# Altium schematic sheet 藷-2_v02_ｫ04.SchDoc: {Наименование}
size 420 x 297 mm; DrawnBy: Булычев; Engineer: {Инженер}; DocumentNumber: СИЭТ 21.02.110.000 Э3; SheetNumber: 4; SheetTotal: 6; Title1str: Плата управления; PageSetup: Record=PageOptions|CenterHorizontal=False|CenterVertical=False|PrintScale=0.95|XCorrection=1.00|YCorrection=1.00|PrintKind=2|BorderSize=5000000|LeftOffset=300|BottomOffset=0|Orientation=2|PaperLength=4200|PaperWidth=2970|Scale=100|PaperSource=15|PrintQuality=-1|MediaType=1|DitherType=10|PaperKind=ISO A3|PrintScaleMode=1; Title2str: (ПУ-2); EngineerName: {Инженер}; DocumentType: Схема электрическая принципиальная; DocumentType1str: {Документ}; DocumentType2str: {Документ}
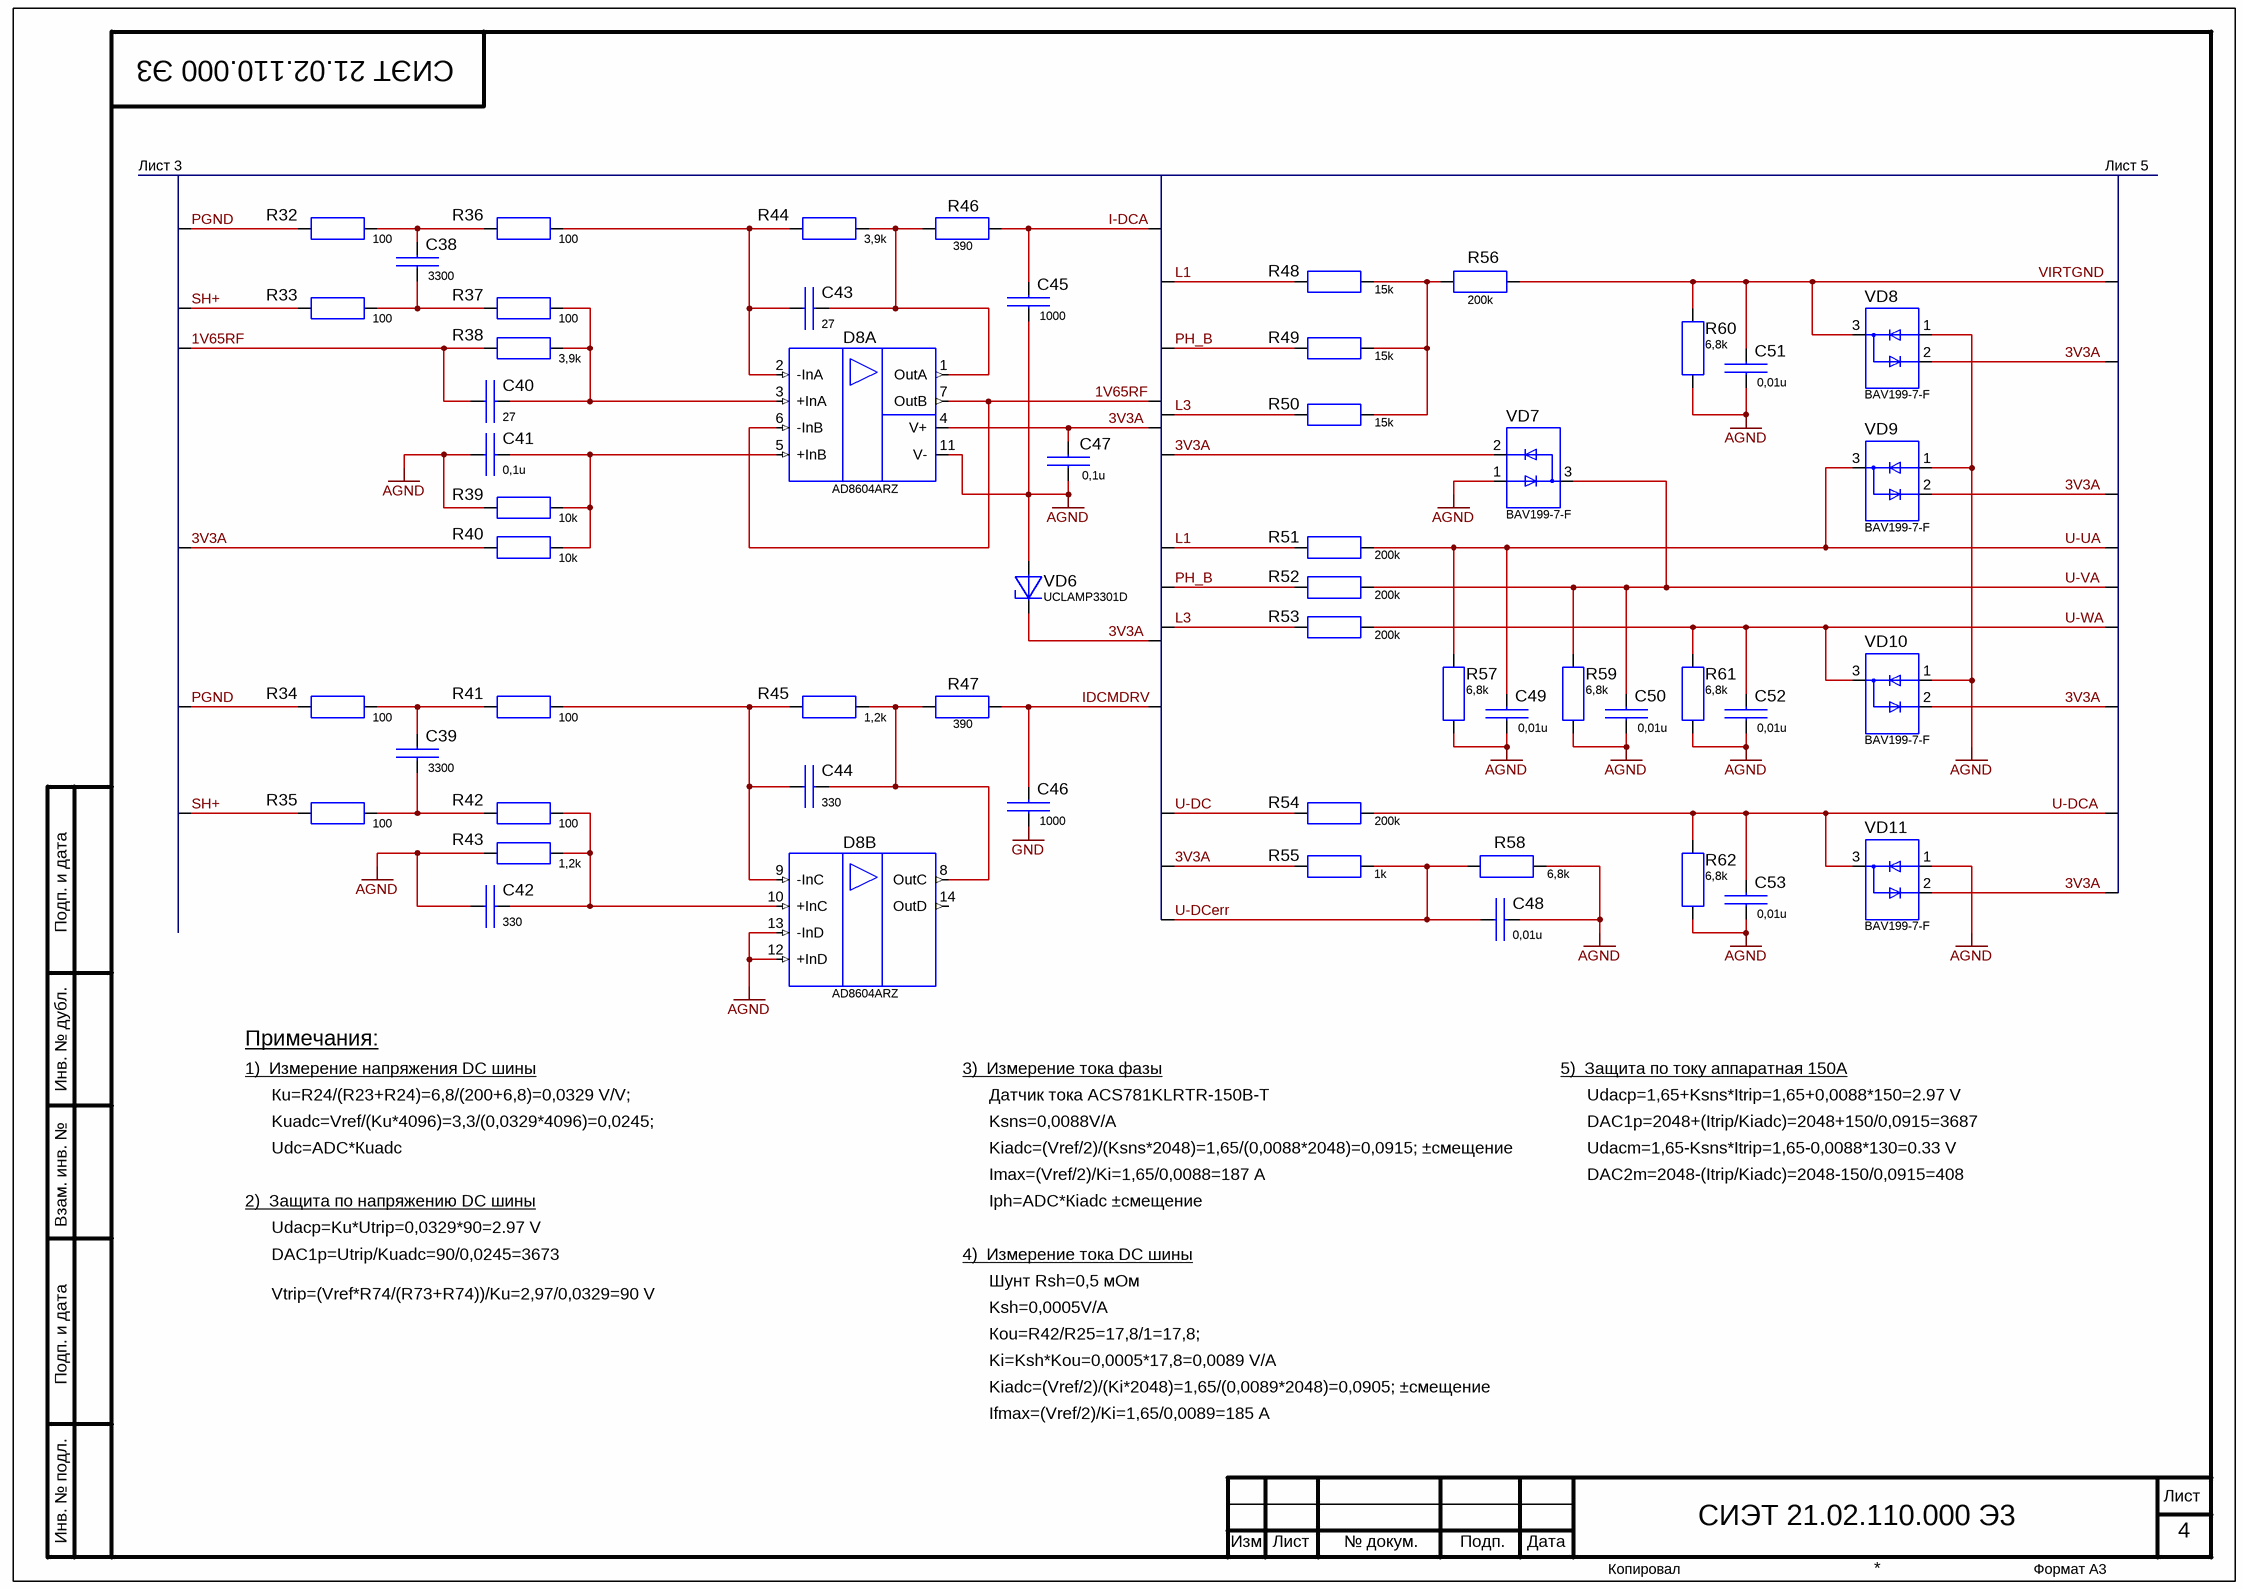
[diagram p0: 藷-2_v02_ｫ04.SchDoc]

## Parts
C38  value 3300  [0603]  (hidden comment: CL10B332KB8NNNC)
C39  value 3300  [0603]  (hidden comment: CL10B332KB8NNNC)
C40  value 27  [0603]  (hidden comment: CL10C270JB8NNNC)
C41  value 0,1u  [0603]  (hidden comment: CL10B104KB8NNNC)
C42  value 330  [0603]  (hidden comment: CL10C331JB8NNNC)
C43  value 27  [0603]  (hidden comment: CL10C270JB8NNNC)
C44  value 330  [0603]  (hidden comment: CL10C331JB8NNNC)
C45  value 1000  [0603]  (hidden comment: CL10C102JB8NNNC)
C46  value 1000  [0603]  (hidden comment: CL10C102JB8NNNC)
C47  value 0,1u  [0603]  (hidden comment: CL10B104KB8NNNC)
C48  value 0,01u  [0603]  (hidden comment: CL10B103KB8NNNC)
C49  value 0,01u  [0603]  (hidden comment: CL10B103KB8NNNC)
C50  value 0,01u  [0603]  (hidden comment: CL10B103KB8NNNC)
C51  value 0,01u  [0603]  (hidden comment: CL10B103KB8NNNC)
C52  value 0,01u  [0603]  (hidden comment: CL10B103KB8NNNC)
C53  value 0,01u  [0603]  (hidden comment: CL10B103KB8NNNC)
D8  AD8604ARZ  [SOIC-14N]  (parts A,B of 2)
R32  value 100  [RC0603]  (hidden comment: RC0603FR-07100RL)
R33  value 100  [RC0603]  (hidden comment: RC0603FR-07100RL)
R34  value 100  [RC0603]  (hidden comment: RC0603FR-07100RL)
R35  value 100  [RC0603]  (hidden comment: RC0603FR-07100RL)
R36  value 100  [RC0603]  (hidden comment: RC0603FR-07100RL)
R37  value 100  [RC0603]  (hidden comment: RC0603FR-07100RL)
R38  value 3,9k  [RC0603]  (hidden comment: RC0603FR-073K9L)
R39  value 10k  [RC0603]  (hidden comment: RC0603FR-0710KL)
R40  value 10k  [RC0603]  (hidden comment: RC0603FR-0710KL)
R41  value 100  [RC0603]  (hidden comment: RC0603FR-07100RL)
R42  value 100  [RC0603]  (hidden comment: RC0603FR-07100RL)
R43  value 1,2k  [RC0603]  (hidden comment: RC0603FR-071K2L)
R44  value 3,9k  [RC0603]  (hidden comment: RC0603FR-073K9L)
R45  value 1,2k  [RC0603]  (hidden comment: RC0603FR-071K2L)
R46  value 390  [RC0603]  (hidden comment: RC0603FR-07390RL)
R47  value 390  [RC0603]  (hidden comment: RC0603FR-07390RL)
R48  value 15k  [RC1206]  (hidden comment: RC1206FR-0715KL)
R49  value 15k  [RC1206]  (hidden comment: RC1206FR-0715KL)
R50  value 15k  [RC1206]  (hidden comment: RC1206FR-0715KL)
R51  value 200k  [RC0805]  (hidden comment: RC0805FR-07200KL)
R52  value 200k  [RC0805]  (hidden comment: RC0805FR-07200KL)
R53  value 200k  [RC0805]  (hidden comment: RC0805FR-07200KL)
R54  value 200k  [RC0805]  (hidden comment: RC0805FR-07200KL)
R55  value 1k  [RC0603]  (hidden comment: RC0603FR-071KL)
R56  value 200k  [RC0805]  (hidden comment: RC0805FR-07200KL)
R57  value 6,8k  [RC0603]  (hidden comment: RC0603FR-076K8L)
R58  value 6,8k  [RC0603]  (hidden comment: RC0603FR-076K8L)
R59  value 6,8k  [RC0603]  (hidden comment: RC0603FR-076K8L)
R60  value 6,8k  [RC0603]  (hidden comment: RC0603FR-076K8L)
R61  value 6,8k  [RC0603]  (hidden comment: RC0603FR-076K8L)
R62  value 6,8k  [RC0603]  (hidden comment: RC0603FR-076K8L)
VD6  UCLAMP3301D  [SOD-323]
VD7  BAV199-7-F  [SOT23-3]
VD8  BAV199-7-F  [SOT23-3]
VD9  BAV199-7-F  [SOT23-3]
VD10  BAV199-7-F  [SOT23-3]
VD11  BAV199-7-F  [SOT23-3]

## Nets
AGND: C41.2 C42.2 C45.1 C47.1 C48.2 C49.2 C50.2 C51.2 C52.2 C53.2 D8.11(V-) D8.12(+InD) D8.13(-InD) R39.1 R43.1 R57.1 R58.1 R59.1 R60.1 R61.1 R62.1 VD6.2(A) VD7.1 VD8.1 VD9.1 VD10.1 VD11.1
GND: C46.1
1V65RF: C40.2 D8.6(-InB) D8.7(OutB) R38.1
3V3A: C47.2 D8.4(V+) R40.1 R55.2 VD6.1(C) VD7.2 VD8.2 VD9.2 VD10.2 VD11.2
I-DCA: C45.2 R46.2
IDCMDRV: C46.2 R47.2
L1: R48.1 R51.1
L3: R50.1 R53.1
PGND: R32.1 R34.1
PH_B: R49.1 R52.1
SH+: R33.1 R35.1
U-DC: R54.1
U-DCA: C53.1 R54.2 R62.2 VD11.3
U-DCerr: C48.1 R55.1 R58.2
U-UA: C49.1 R51.2 R57.2 VD9.3
U-VA: C50.1 R52.2 R59.2 VD7.3
U-WA: C52.1 R53.2 R61.2 VD10.3
VIRTGND: C51.1 R56.2 R60.2 VD8.3
NetC38_1: C38.1 R33.2 R37.1
NetC38_2: C38.2 R32.2 R36.1
NetC39_1: C39.1 R35.2 R42.1
NetC39_2: C39.2 R34.2 R41.1
NetC40_1: C40.1 D8.3(+InA) R37.2 R38.2
NetC41_1: C41.1 D8.5(+InB) R39.2 R40.2
NetC42_1: C42.1 D8.10(+InC) R42.2 R43.2
NetC43_1: C43.1 D8.1(OutA) R44.2 R46.1
NetC43_2: C43.2 D8.2(-InA) R36.2 R44.1
NetC44_1: C44.1 D8.9(-InC) R41.2 R45.1
NetC44_2: C44.2 D8.8(OutC) R45.2 R47.1
NetR48_2: R48.2 R49.2 R50.2 R56.1

Not connected (* = marked no-connect by the designer): D8 14(OutD)

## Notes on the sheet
- Лист 3
- Лист 5
- Примечания:
- 1)  Измерение напряжения DC шины
- Кu=R24/(R23+R24)=6,8/(200+6,8)=0,0329 V/V;
- Kuadc=Vref/(Ku*4096)=3,3/(0,0329*4096)=0,0245;
- 3)  Измерение тока фазы
- Датчик тока ACS781KLRTR-150B-T
- Ksns=0,0088V/A
- 5)  Защита по току аппаратная 150A
- Udacp=1,65+Ksns*Itrip=1,65+0,0088*150=2.97 V
- DAC1p=2048+(Itrip/Kiadc)=2048+150/0,0915=3687
- 2)  Защита по напряжению DC шины
- Udc=ADC*Кuadc
- Imax=(Vref/2)/Ki=1,65/0,0088=187 A
- Kiadc=(Vref/2)/(Ksns*2048)=1,65/(0,0088*2048)=0,0915; ±смещение
- Iph=ADC*Кiadc ±смещение
- Udacm=1,65-Ksns*Itrip=1,65-0,0088*130=0.33 V
- DAC2m=2048-(Itrip/Kiadc)=2048-150/0,0915=408
- Udacp=Ku*Utrip=0,0329*90=2.97 V
- DAC1p=Utrip/Kuadc=90/0,0245=3673
- 4)  Измерение тока DC шины
- Vtrip=(Vref*R74/(R73+R74))/Ku=2,97/0,0329=90 V
- Шунт Rsh=0,5 мОм
- Кou=R42/R25=17,8/1=17,8;
- Ksh=0,0005V/A
- Ki=Ksh*Kou=0,0005*17,8=0,0089 V/A
- Kiadc=(Vref/2)/(Ki*2048)=1,65/(0,0089*2048)=0,0905; ±смещение
- Ifmax=(Vref/2)/Ki=1,65/0,0089=185 A

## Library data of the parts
C38 C39 C48-C53 = CL10B103KB8NNNC: 0603 - 50V - 0,01uF; Pdf: GeneralCapacitors_12022.pdf; Voltage: 50В; Type: CL10; Tolerance: ±10%; ТКЕ: X7R
C40 C42 C43 = CL10C120JB8NNNC: 0603 - 50V - 12pF; Pdf: GeneralCapacitors_12022.pdf; Voltage: 50В; Type: CL10; Tolerance: ±5%; ТКЕ: NP0
C41 C47 = CL10B104KB8NNNC: 0603 - 50V - 0,1uF; Pdf: GeneralCapacitors_12022.pdf; Voltage: 50В; Type: CL10; Tolerance: ±10%; ТКЕ: X7R
C44 = CL10C151JB8NNNC: 0603 - 50V - 150pF; Pdf: GeneralCapacitors_12022.pdf; Voltage: 50В; Type: CL10C102JB8NNNC; Tolerance: ±5%; ТКЕ: NP0
C45 C46 = CL10B103KB8NNNC: 0603 - 50V - 0,01uF; Pdf: GeneralCapacitors_12022.pdf; Voltage: 50В; Type: CL10; Tolerance: ±5%; ТКЕ: NP0
D8 = AD8604ARZ: Precision Low Noise CMOS Rail-to-Rail OpAmp; Pdf: AD8601_8602_8604.pdf; Корпус: 14-Lead SOIC_N
R32-R47 R55 R57-R62 = RC0603: 0603, 0.1W, Thick Film Chip Resistors; Power: 0,1 Вт; Tolerance: ±1%; Pdf: RC0603.pdf; Корпус: 0603; ТКС: ±100 ppm/K
R48-R50 = RC1206: 1206, 0.25W, Thick Film Chip Resistors; Power: 0,25 Вт; Tolerance: ±1%; Pdf: RC1206.pdf; Корпус: 1206; ТКС: ±100 ppm/K
R51-R54 R56 = RC0805: 0805, 0.125W, Thick Film Chip Resistors; Power: 0,125 Вт; Tolerance: ±1%; Pdf: RC0805.pdf; Корпус: 0805; ТКС: ±100 ppm/K
VD6 = UCLAMP3301D: Transient Volnage Supressor Power 100 W; Pdf: UCLAMP3301D.pdf; КД: UCLAMP3301D.TCT; Замена 1: AQ4020-01FTG; Замена 2: SP4020-01FTG; Замена 3: BZT52C3V6S-TP
VD7-VD11 = BAV199: DUAL SURFACE MOUNT LOW LEAKAGE DIODE; Pdf: BAV199.pdf; Корпус: SOT323; Замена 1: BAV199E6433HTMA1; Замена 2: BAV199LT1G; Замена 3: BAV199,215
